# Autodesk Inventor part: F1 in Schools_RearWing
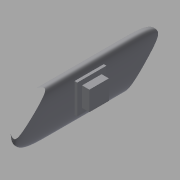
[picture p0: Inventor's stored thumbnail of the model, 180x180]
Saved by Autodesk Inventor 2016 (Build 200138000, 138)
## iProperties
Created: 2015-12
Part Number: F1 in Schools_RearWing
Material: Generic
Document SubType Name: Modeling
Designer: Autodesk Inc.
Density: 1 g/cm^3
Appearance: Default
Author: Autodesk Inc
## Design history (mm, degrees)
workplane "Work Plane1"
sketch "Sketch1"
  geometry: L1 (14, 20)-(14, 0) reference; L2 (-6, 0)-(14, 0) reference; L3 (-6, 0)-(-6, 20) reference; L4 (-6, 20)-(14, 20) reference; 2 further points
  dimensions: "d0" = 50 distance from line of point (44, 10) L3
  node "Reference1"
feature "Form1"
workplane "Work Plane3"
sketch "Sketch3"
  geometry: L1 (-4, 19)-(-4, 11) reference; L2 (-4, 11)-(4, 11) reference; L3 (4, 11)-(4, 19) reference; L4 (4, 19)-(-4, 19) reference; L5 (6, 9)-(-6, 9); L6 (-6, 9)-(-6, 21); L7 (-6, 21)-(6, 21); L8 (6, 21)-(6, 9); 1 further point
  constraints: 8 end point, 3 other
  dimensions: "d7" = 2 distance between parallel lines of L5 L2
extrude "Extrusion2" join sketch "Sketch3" distance "d8" = 1; taper "d10" = 0 deg; dims "d9" = 0.5, "d11" = 0
sketch "Sketch4"
  geometry: L1 (-11, 4)-(-11, -4) reference; L2 (-11, -4)-(-19, -4) reference; L3 (-19, -4)-(-19, 4) reference; L4 (-19, 4)-(-11, 4) reference; 1 further point
extrude "Extrusion3" new body sketch "Sketch4" distance "d12" = 3; taper "d14" = 0 deg; dims "d13" = 2.5, "d15" = 0
combine "Combine1"
node "Reference2"
node "Reference3"
node "Reference4"
node "Reference5"
body "Solid2"
body "Solid1"
